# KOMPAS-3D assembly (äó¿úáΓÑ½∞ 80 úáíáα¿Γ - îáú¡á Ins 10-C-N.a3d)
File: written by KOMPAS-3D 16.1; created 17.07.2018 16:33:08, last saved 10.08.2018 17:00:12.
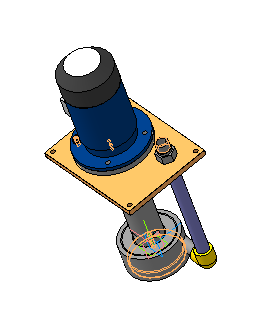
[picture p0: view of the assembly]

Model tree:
1. Булева операция:11
2. Булева операция:12
3. Сечение поверхностью:6  (labels: Полипропилен  ГОСТ 26996-86; Двигатель 80 габарит)
     Расстояние = 1.5

Referenced files in Z:\Магна\Магна Ins\Магна ins 10\М10-00.00.000\3Д\: М10-00.00.002 - Крышка.m3d, М10-00.00.001 - Импеллер Магна10.m3d, М10-00.00.003 - Защитная втулка.m3d, Двигатель 80 габарит - Корпус.a3d, М10-00.15.001-02 - Вал.m3d, М10-00.20.000 - Корпус.cdw, М10-00.00.002 - Крышка.cdw, М10-00.00.001 - Импеллер Магна10.cdw, М10-00.00.003 - Защитная втулка.cdw
Referenced files in Z:\1 ПКИ 3D\РТИ\Кольца уплотнительные  плоские\: Кольцо плоское уплотнительное 10-23-25 EPDM.m3d
Referenced files in Z:\АкваProf\АкваProf 190\3Д модель\: М10А-00.00.003 - Втулка ответная.m3d
Referenced files in Z:\1 ПКИ 3D\Двигатели\АИР\: Электродвигатель АИР 80А2 IM 3081 1,5кВт 3000 об..m3d
Referenced files in D:\Отработать\2 Насос с закрытым колесом\Магна INS 11\: М11-00.01.002 - Фиксатор.m3d
Referenced files in C:\Program Files\ASCON\KOMPAS-3D V16\Libs\PartLib\DATA\vault\Methods\Kompas\3D\: PLib_Washer_1_712.m3d, PLib_Washer_2_712.m3d, PLib_Nut_OST92_900.m3d
Referenced files in C:\Program Files\ASCON\KOMPAS-3D V16\Libs\PartLib\DATA\VAULT\Methods\kompas\3d\: PLib_Bolt_1_900.m3d
Referenced files: graphic.tdp
Referenced files in Z:\Магна\Магна Ins\Магна ins 11\Магна N\Чертежи\: М11-00.01.002 - Фиксатор.cdw
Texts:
  Body Specification ( left align )
  Body Specificaton ( centered )
  @100~)3xA3
  (+) М10-00.20.000 Корпус
  @100~)2xA4См. заказ
  (+) М10-00.00.002 Крышка
  Импеллер Магна10
  Закладная М10
  (Заготовка для М10-00.00.001)
  Закладная М10 / (Заготовка для М10-00.00.001)
  (-) М10-00.00.001 Импеллер Магна10
  Кольцо плоское уплотнительное
  Кольцо плоское уплотнительное / 10-23-25 EPDM
  (-) Кольцо плоское уплотнительное / 10-23-25 EPDM
  (-) М10-00.00.003 Защитная втулка
  (-) М10А-00.00.003-01 Втулка ответная
  АИР 80А2 IM 3081 IP55 ф."IEK"
  Электродвигатель / АИР 80А2 IM 3081 IP55 ф."IEK"
  (-) Электродвигатель АИР 80А2 1,5кВт IM 3081 IP55 ф."Элком"
  (-) М11-00.01.002 Фиксатор
  (-) М10-00.15.001 Вал
  Сталь 12Х18Н10Т ГОСТ 5632-72
  Шайба C.10.21 ГОСТ 11371-78
  Крепежное изделие ГОСТ
  (-) Шайба C.10.21 ГОСТ 11371-78 (1)
  (-) Шайба C.10.21 ГОСТ 11371-78 (2)
  Шайба 10 ГОСТ 6402-70
  (-) Шайба 10 ГОСТ 6402-70
  Гайка М10-6H.21.12Х18Н10Т ГОСТ 5915-70
  bcut1
  hole1
  hcut1
  hole2
  cut1
  (-) Гайка М10-6H.21.12Х18Н10Т ГОСТ 5915-70
  Болт М10-6gx55.21.12Х18Н10Т ГОСТ 7798-70
  (-) Болт М10-6gx55.21.12Х18Н10Т ГОСТ 7798-70
  Магна Ins 10-C-N
  ГОСТ 11371-78
  ГОСТ 6402-70
  ГОСТ 5915-70
  ГОСТ 7798-70
  М10-6gx55.21.12Х18Н10Т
